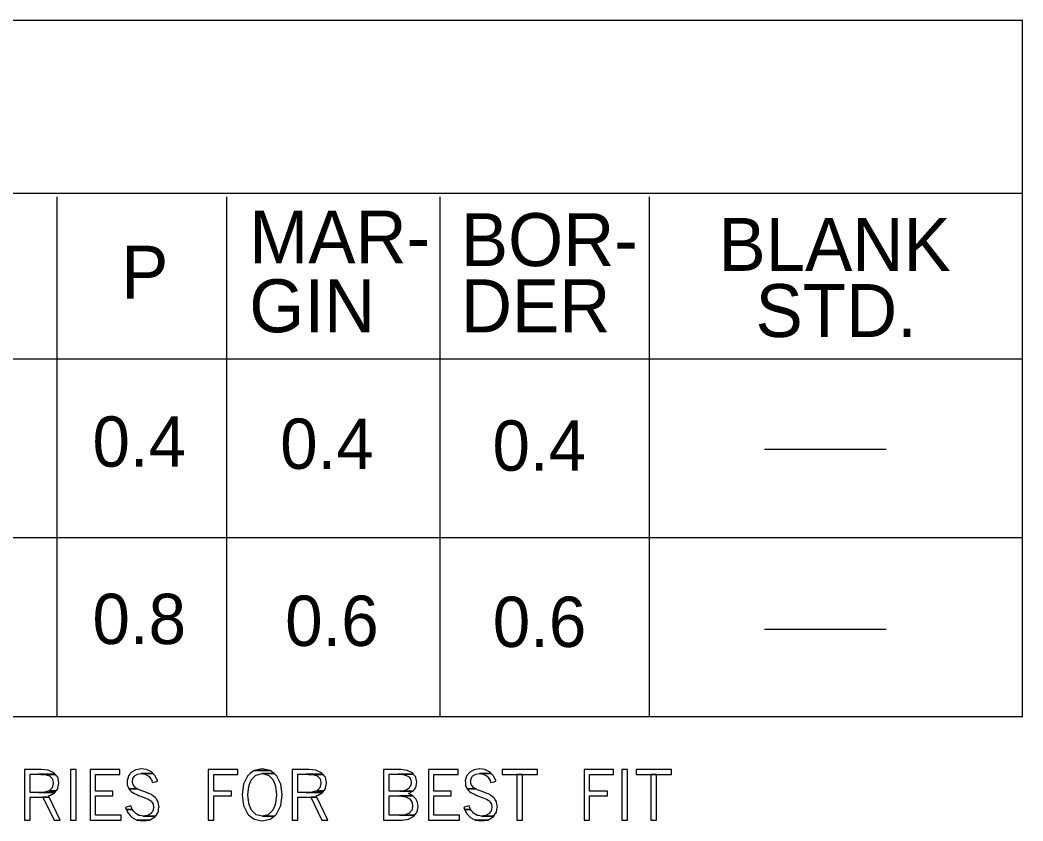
# Model space of a CAD drawing. Extents: x 0.013 to 0.187, y -0.092 to 0.261.
# Drawn here: x 0.13917 to 0.18651, y 0.0569 to 0.09473 of the extents above; entities that cross this region are included whole.
import ezdxf

# ---------------------------------------------------------------- set-up
doc = ezdxf.new("R2010")
doc.units = 0
doc.layers.add('3', color=7, linetype='Continuous')

msp = doc.modelspace()

# ---------------------------------------------------------------- linework, layer by layer
at = {"layer": '3'}
for p, q in [((0.032451, 0.094728), (0.186512, 0.094728)), ((0.186473, 0.094707), (0.186473, 0.061821)), ((0.186512, 0.086538), (0.032451, 0.086538)), ((0.140908, 0.086386), (0.140908, 0.061842)), ((0.148908, 0.086386), (0.148908, 0.061842)), ((0.158976, 0.086386), (0.158976, 0.061842)), ((0.168869, 0.086386), (0.168869, 0.061842)), ((0.032384, 0.078726), (0.186512, 0.078726)), ((0.174312, 0.074459), (0.180062, 0.074459)), ((0.032451, 0.070284), (0.186512, 0.070284)), ((0.174312, 0.065959), (0.180062, 0.065959)), ((0.032519, 0.061842), (0.186512, 0.061842))]:
    msp.add_line(p, q, dxfattribs=at)
for points in [[(0.139376, 0.058024), (0.139376, 0.056942), (0.139636, 0.056942), (0.139636, 0.058024), (0.140533, 0.058024), (0.140503, 0.058086), (0.140605, 0.058122), (0.140792, 0.058228), (0.140806, 0.058246), (0.139636, 0.058246), (0.139636, 0.058249), (0.139636, 0.058264), (0.139636, 0.058332), (0.139636, 0.058428), (0.139636, 0.058472), (0.139636, 0.058676), (0.139636, 0.058696), (0.139636, 0.058887), (0.139636, 0.058964), (0.139636, 0.059034), (0.139636, 0.059093), (0.139636, 0.059104), (0.139636, 0.059106), (0.140828, 0.059106), (0.140768, 0.059179), (0.140492, 0.059298), (0.140175, 0.059326), (0.140046, 0.059329), (0.139376, 0.059329), (0.139376, 0.059326), (0.139376, 0.059298), (0.139376, 0.059179), (0.139376, 0.059106), (0.139376, 0.059104), (0.139376, 0.059093), (0.139376, 0.059034), (0.139376, 0.058964), (0.139376, 0.058887), (0.139376, 0.058696), (0.139376, 0.058676), (0.139376, 0.058472), (0.139376, 0.058428), (0.139376, 0.058332), (0.139376, 0.058264), (0.139376, 0.058249), (0.139376, 0.058246), (0.139376, 0.058228), (0.139376, 0.058122), (0.139376, 0.058086)], [(0.141548, 0.059329), (0.141548, 0.056942), (0.141816, 0.056942), (0.141816, 0.059329)], [(0.142472, 0.057172), (0.142472, 0.056942), (0.143935, 0.056942), (0.143935, 0.057172), (0.142734, 0.057172), (0.142734, 0.058085), (0.143546, 0.058085), (0.143546, 0.058306), (0.142734, 0.058306), (0.142734, 0.059103), (0.143879, 0.059103), (0.143879, 0.059329), (0.142472, 0.059329), (0.142472, 0.059103), (0.142472, 0.058306), (0.142472, 0.058085)], [(0.14428, 0.058465), (0.144302, 0.058415), (0.144717, 0.058415), (0.144621, 0.058465), (0.144532, 0.05857), (0.144499, 0.058609), (0.144476, 0.058715), (0.144467, 0.058756), (0.144472, 0.058784), (0.144475, 0.058806), (0.144484, 0.058856), (0.144485, 0.058862), (0.144493, 0.05891), (0.144563, 0.059016), (0.144575, 0.059034), (0.144586, 0.059041), (0.144602, 0.059051), (0.144712, 0.059118), (0.144715, 0.059119), (0.144885, 0.059146), (0.145444, 0.059146), (0.145385, 0.059208), (0.145365, 0.059229), (0.145165, 0.059325), (0.145133, 0.05934), (0.144879, 0.059367), (0.144879, 0.059367), (0.144722, 0.05934), (0.144632, 0.059325), (0.14446, 0.059229), (0.144422, 0.059208), (0.144372, 0.059146), (0.14435, 0.059119), (0.144349, 0.059118), (0.144294, 0.059051), (0.144286, 0.059041), (0.144283, 0.059034), (0.144278, 0.059016), (0.144247, 0.05891), (0.144233, 0.058862), (0.144231, 0.058856), (0.144216, 0.058806), (0.144217, 0.058784), (0.144219, 0.058756), (0.144222, 0.058715), (0.144229, 0.058609), (0.144232, 0.05857)], [(0.14805, 0.058083), (0.14805, 0.056942), (0.148312, 0.056942), (0.148312, 0.058083), (0.149153, 0.058083), (0.149153, 0.058308), (0.148312, 0.058308), (0.148312, 0.059103), (0.149448, 0.059103), (0.149448, 0.059329), (0.14805, 0.059329), (0.14805, 0.059103), (0.14805, 0.058308)], [(0.150225, 0.05698), (0.150596, 0.056903), (0.150968, 0.05698), (0.151156, 0.057133), (0.150596, 0.057133), (0.150314, 0.057197), (0.150285, 0.057225), (0.150092, 0.057409), (0.150002, 0.057637), (0.149963, 0.057738), (0.149921, 0.058135), (0.149963, 0.058532), (0.150002, 0.058633), (0.150092, 0.058861), (0.150285, 0.059045), (0.150314, 0.059073), (0.150596, 0.059138), (0.151156, 0.059138), (0.150968, 0.05929), (0.150225, 0.05929), (0.150036, 0.059138), (0.149956, 0.059073), (0.149922, 0.059045), (0.149831, 0.058861), (0.149718, 0.058633), (0.149705, 0.058532), (0.149653, 0.058135), (0.149705, 0.057738), (0.149718, 0.057637), (0.149831, 0.057409), (0.149922, 0.057225), (0.149956, 0.057197), (0.150036, 0.057133)], [(0.150596, 0.059367), (0.150225, 0.05929), (0.150968, 0.05929)], [(0.152013, 0.058024), (0.152013, 0.056942), (0.152272, 0.056942), (0.152272, 0.058024), (0.15317, 0.058024), (0.15314, 0.058086), (0.153242, 0.058122), (0.153429, 0.058228), (0.153443, 0.058246), (0.152272, 0.058246), (0.152272, 0.058249), (0.152272, 0.058264), (0.152272, 0.058332), (0.152272, 0.058428), (0.152272, 0.058472), (0.152272, 0.058676), (0.152272, 0.058696), (0.152272, 0.058887), (0.152272, 0.058964), (0.152272, 0.059034), (0.152272, 0.059093), (0.152272, 0.059104), (0.152272, 0.059106), (0.153465, 0.059106), (0.153405, 0.059179), (0.153129, 0.059298), (0.152812, 0.059326), (0.152683, 0.059329), (0.152013, 0.059329), (0.152013, 0.059326), (0.152013, 0.059298), (0.152013, 0.059179), (0.152013, 0.059106), (0.152013, 0.059104), (0.152013, 0.059093), (0.152013, 0.059034), (0.152013, 0.058964), (0.152013, 0.058887), (0.152013, 0.058696), (0.152013, 0.058676), (0.152013, 0.058472), (0.152013, 0.058428), (0.152013, 0.058332), (0.152013, 0.058264), (0.152013, 0.058249), (0.152013, 0.058246), (0.152013, 0.058228), (0.152013, 0.058122), (0.152013, 0.058086)], [(0.156327, 0.056945), (0.156327, 0.056942), (0.157052, 0.056942), (0.157206, 0.056945), (0.157501, 0.056988), (0.157761, 0.057128), (0.157794, 0.057172), (0.156587, 0.057172), (0.156587, 0.057175), (0.156587, 0.057193), (0.156587, 0.057266), (0.156587, 0.057332), (0.156587, 0.05741), (0.156587, 0.057568), (0.156587, 0.057589), (0.156587, 0.057782), (0.156587, 0.057788), (0.156587, 0.057944), (0.156587, 0.057969), (0.156587, 0.058045), (0.156587, 0.058081), (0.156587, 0.058084), (0.157715, 0.058084), (0.157701, 0.058098), (0.15757, 0.058172), (0.157506, 0.0582), (0.157571, 0.058226), (0.157676, 0.058288), (0.157695, 0.058306), (0.156587, 0.058306), (0.156587, 0.058312), (0.156587, 0.058346), (0.156587, 0.058396), (0.156587, 0.05844), (0.156587, 0.058542), (0.156587, 0.058576), (0.156587, 0.058728), (0.156587, 0.058744), (0.156587, 0.058877), (0.156587, 0.05897), (0.156587, 0.059003), (0.156587, 0.059087), (0.156587, 0.059113), (0.156587, 0.059114), (0.15774, 0.059114), (0.15769, 0.059177), (0.157445, 0.059288), (0.157152, 0.059326), (0.156973, 0.059329), (0.156327, 0.059329), (0.156327, 0.059326), (0.156327, 0.059288), (0.156327, 0.059177), (0.156327, 0.059114), (0.156327, 0.059113), (0.156327, 0.059087), (0.156327, 0.059003), (0.156327, 0.05897), (0.156327, 0.058877), (0.156327, 0.058744), (0.156327, 0.058728), (0.156327, 0.058576), (0.156327, 0.058542), (0.156327, 0.05844), (0.156327, 0.058396), (0.156327, 0.058346), (0.156327, 0.058312), (0.156327, 0.058306), (0.156327, 0.058288), (0.156327, 0.058226), (0.156327, 0.0582), (0.156327, 0.058172), (0.156327, 0.058098), (0.156327, 0.058084), (0.156327, 0.058081), (0.156327, 0.058045), (0.156327, 0.057969), (0.156327, 0.057944), (0.156327, 0.057788), (0.156327, 0.057782), (0.156327, 0.057589), (0.156327, 0.057568), (0.156327, 0.05741), (0.156327, 0.057332), (0.156327, 0.057266), (0.156327, 0.057193), (0.156327, 0.057175), (0.156327, 0.057172), (0.156327, 0.057128), (0.156327, 0.056988)], [(0.158442, 0.057172), (0.158442, 0.056942), (0.159905, 0.056942), (0.159905, 0.057172), (0.158704, 0.057172), (0.158704, 0.058085), (0.159516, 0.058085), (0.159516, 0.058306), (0.158704, 0.058306), (0.158704, 0.059103), (0.159849, 0.059103), (0.159849, 0.059329), (0.158442, 0.059329), (0.158442, 0.059103), (0.158442, 0.058306), (0.158442, 0.058085)], [(0.16025, 0.058465), (0.160272, 0.058415), (0.160687, 0.058415), (0.160591, 0.058465), (0.160502, 0.05857), (0.160469, 0.058609), (0.160446, 0.058715), (0.160437, 0.058756), (0.160442, 0.058784), (0.160445, 0.058806), (0.160454, 0.058856), (0.160455, 0.058862), (0.160463, 0.05891), (0.160533, 0.059016), (0.160545, 0.059034), (0.160556, 0.059041), (0.160572, 0.059051), (0.160682, 0.059118), (0.160685, 0.059119), (0.160855, 0.059146), (0.161413, 0.059146), (0.161355, 0.059208), (0.161335, 0.059229), (0.161135, 0.059325), (0.161103, 0.05934), (0.160849, 0.059367), (0.160848, 0.059367), (0.160691, 0.05934), (0.160602, 0.059325), (0.16043, 0.059229), (0.160392, 0.059208), (0.160341, 0.059146), (0.16032, 0.059119), (0.160318, 0.059118), (0.160263, 0.059051), (0.160255, 0.059041), (0.160253, 0.059034), (0.160248, 0.059016), (0.160217, 0.05891), (0.160202, 0.058862), (0.160201, 0.058856), (0.160186, 0.058806), (0.160187, 0.058784), (0.160189, 0.058756), (0.160192, 0.058715), (0.160199, 0.058609), (0.160202, 0.05857)], [(0.161925, 0.059329), (0.161925, 0.059099), (0.163587, 0.059099), (0.163587, 0.059329)], [(0.165791, 0.058083), (0.165791, 0.056942), (0.166053, 0.056942), (0.166053, 0.058083), (0.166895, 0.058083), (0.166895, 0.058308), (0.166053, 0.058308), (0.166053, 0.059103), (0.167189, 0.059103), (0.167189, 0.059329), (0.165791, 0.059329), (0.165791, 0.059103), (0.165791, 0.058308)], [(0.167578, 0.059329), (0.167578, 0.056942), (0.167845, 0.056942), (0.167845, 0.059329)], [(0.168255, 0.059329), (0.168255, 0.059099), (0.169917, 0.059099), (0.169917, 0.059329)], [(0.140154, 0.059104), (0.140342, 0.059093), (0.14084, 0.059093), (0.140831, 0.059104), (0.14083, 0.059104), (0.140828, 0.059106), (0.140043, 0.059106)], [(0.140642, 0.058428), (0.140542, 0.058332), (0.140873, 0.058332), (0.140947, 0.058428), (0.140956, 0.058472), (0.140995, 0.058676), (0.140999, 0.058696), (0.140962, 0.058887), (0.140947, 0.058964), (0.140889, 0.059034), (0.14084, 0.059093), (0.140341, 0.059093), (0.14055, 0.059034), (0.140616, 0.058964), (0.140691, 0.058887), (0.140728, 0.058696), (0.140732, 0.058676), (0.140687, 0.058472)], [(0.145404, 0.058756), (0.14542, 0.058715), (0.145561, 0.058756), (0.145658, 0.058784), (0.145651, 0.058806), (0.145635, 0.058856), (0.145633, 0.058862), (0.145608, 0.05891), (0.145552, 0.059016), (0.145543, 0.059034), (0.145539, 0.059041), (0.145534, 0.059051), (0.14547, 0.059118), (0.145469, 0.059119), (0.145444, 0.059146), (0.144885, 0.059146), (0.145057, 0.059119), (0.145067, 0.059118), (0.145185, 0.059051), (0.145203, 0.059041), (0.145215, 0.059034), (0.145248, 0.059016), (0.145326, 0.05891), (0.145361, 0.058862), (0.145366, 0.058856), (0.145385, 0.058806), (0.145394, 0.058784)], [(0.150877, 0.057197), (0.150596, 0.057133), (0.151156, 0.057133), (0.151237, 0.057197), (0.151236, 0.057197), (0.151271, 0.057225), (0.151362, 0.057409), (0.151475, 0.057637), (0.151488, 0.057738), (0.151539, 0.058135), (0.151488, 0.058532), (0.151475, 0.058633), (0.151362, 0.058861), (0.151271, 0.059045), (0.151237, 0.059073), (0.151236, 0.059073), (0.151156, 0.059138), (0.150595, 0.059138), (0.150877, 0.059073), (0.150906, 0.059045), (0.151099, 0.058861), (0.151189, 0.058633), (0.151229, 0.058532), (0.151271, 0.058135), (0.151229, 0.057738), (0.151189, 0.057637), (0.151099, 0.057409), (0.150906, 0.057225)], [(0.152791, 0.059104), (0.152979, 0.059093), (0.153477, 0.059093), (0.153467, 0.059104), (0.153467, 0.059104), (0.153465, 0.059106), (0.15268, 0.059106)], [(0.153278, 0.058428), (0.153179, 0.058332), (0.15351, 0.058332), (0.153584, 0.058428), (0.153593, 0.058472), (0.153632, 0.058676), (0.153636, 0.058696), (0.153599, 0.058887), (0.153584, 0.058964), (0.153526, 0.059034), (0.153477, 0.059093), (0.152978, 0.059093), (0.153186, 0.059034), (0.153253, 0.058964), (0.153328, 0.058887), (0.153365, 0.058696), (0.153369, 0.058676), (0.153324, 0.058472)], [(0.157022, 0.059114), (0.157123, 0.059113), (0.15774, 0.059113), (0.15774, 0.059114)], [(0.157359, 0.058346), (0.157191, 0.058312), (0.157701, 0.058312), (0.157737, 0.058346), (0.15779, 0.058396), (0.157814, 0.05844), (0.15787, 0.058542), (0.157875, 0.058576), (0.157874, 0.058576), (0.157895, 0.058728), (0.157898, 0.058744), (0.157871, 0.058877), (0.157853, 0.05897), (0.157827, 0.059003), (0.157761, 0.059087), (0.15774, 0.059113), (0.157123, 0.059113), (0.15732, 0.059087), (0.157507, 0.059003), (0.157531, 0.05897), (0.157601, 0.058877), (0.157627, 0.058744), (0.15763, 0.058728), (0.157608, 0.058576), (0.157587, 0.058542), (0.157522, 0.05844), (0.157446, 0.058396)], [(0.161374, 0.058756), (0.16139, 0.058715), (0.161531, 0.058756), (0.161628, 0.058784), (0.161621, 0.058806), (0.161605, 0.058856), (0.161603, 0.058862), (0.161578, 0.05891), (0.161522, 0.059016), (0.161513, 0.059034), (0.161509, 0.059041), (0.161504, 0.059051), (0.16144, 0.059118), (0.161439, 0.059119), (0.161413, 0.059146), (0.160854, 0.059146), (0.161027, 0.059119), (0.161037, 0.059118), (0.161155, 0.059051), (0.161173, 0.059041), (0.161185, 0.059034), (0.161218, 0.059016), (0.161295, 0.05891), (0.161331, 0.058862), (0.161336, 0.058856), (0.161355, 0.058806), (0.161363, 0.058784)], [(0.16262, 0.059099), (0.16262, 0.056942), (0.162891, 0.056942), (0.162891, 0.059099)], [(0.16895, 0.059099), (0.16895, 0.056942), (0.16922, 0.056942), (0.16922, 0.059099)], [(0.14012, 0.058249), (0.140034, 0.058246), (0.140806, 0.058246), (0.140809, 0.058249), (0.140821, 0.058264), (0.140873, 0.058332), (0.140542, 0.058332), (0.140324, 0.058264)], [(0.145168, 0.057156), (0.144976, 0.057131), (0.145563, 0.057131), (0.14558, 0.057156), (0.145586, 0.057166), (0.145633, 0.057236), (0.145642, 0.057251), (0.145642, 0.057251), (0.145654, 0.057269), (0.145687, 0.057318), (0.145696, 0.057373), (0.145702, 0.057406), (0.145709, 0.057446), (0.145724, 0.057531), (0.145725, 0.057541), (0.145726, 0.057546), (0.14573, 0.057563), (0.145709, 0.057702), (0.145694, 0.057798), (0.145675, 0.05783), (0.145612, 0.057933), (0.145571, 0.058001), (0.145547, 0.058018), (0.145418, 0.058113), (0.145374, 0.058145), (0.145249, 0.058198), (0.14513, 0.05825), (0.145009, 0.058293), (0.144828, 0.058359), (0.144717, 0.058415), (0.144302, 0.058415), (0.144354, 0.058359), (0.144415, 0.058293), (0.144484, 0.05825), (0.144564, 0.058198), (0.144686, 0.058145), (0.14476, 0.058113), (0.145018, 0.058018), (0.145056, 0.058001), (0.145215, 0.057933), (0.145368, 0.05783), (0.145389, 0.057798), (0.14545, 0.057702), (0.145471, 0.057563), (0.145474, 0.057546), (0.145473, 0.057541), (0.14547, 0.057531), (0.145453, 0.057446), (0.145444, 0.057406), (0.145438, 0.057373), (0.145393, 0.057318), (0.145353, 0.057269), (0.145338, 0.057251), (0.145326, 0.057236), (0.145187, 0.057166)], [(0.152757, 0.058249), (0.152671, 0.058246), (0.153443, 0.058246), (0.153446, 0.058249), (0.153457, 0.058264), (0.15351, 0.058332), (0.153178, 0.058332), (0.152961, 0.058264)], [(0.15719, 0.058312), (0.157095, 0.058306), (0.157695, 0.058306), (0.157701, 0.058312)], [(0.161137, 0.057156), (0.160946, 0.057131), (0.161533, 0.057131), (0.16155, 0.057156), (0.161556, 0.057166), (0.161602, 0.057236), (0.161612, 0.057251), (0.161612, 0.057251), (0.161624, 0.057269), (0.161657, 0.057318), (0.161666, 0.057373), (0.161672, 0.057406), (0.161679, 0.057446), (0.161694, 0.057531), (0.161695, 0.057541), (0.161696, 0.057546), (0.161699, 0.057563), (0.161678, 0.057702), (0.161664, 0.057798), (0.161645, 0.05783), (0.161582, 0.057933), (0.161541, 0.058001), (0.161517, 0.058018), (0.161387, 0.058113), (0.161344, 0.058145), (0.161219, 0.058198), (0.1611, 0.05825), (0.160979, 0.058293), (0.160798, 0.058359), (0.160687, 0.058415), (0.160272, 0.058415), (0.160324, 0.058359), (0.160385, 0.058293), (0.160454, 0.05825), (0.160534, 0.058198), (0.160656, 0.058145), (0.16073, 0.058113), (0.160988, 0.058018), (0.161026, 0.058001), (0.161185, 0.057933), (0.161338, 0.05783), (0.161358, 0.057798), (0.16142, 0.057702), (0.161441, 0.057563), (0.161444, 0.057546), (0.161442, 0.057541), (0.16144, 0.057531), (0.161423, 0.057446), (0.161414, 0.057406), (0.161408, 0.057373), (0.161363, 0.057318), (0.161323, 0.057269), (0.161308, 0.057251), (0.161296, 0.057236), (0.161157, 0.057166)], [(0.140249, 0.058024), (0.140772, 0.056942), (0.141063, 0.056942), (0.140533, 0.058024)], [(0.152886, 0.058024), (0.153409, 0.056942), (0.1537, 0.056942), (0.15317, 0.058024)], [(0.157343, 0.057193), (0.157169, 0.057175), (0.157796, 0.057175), (0.15781, 0.057193), (0.157865, 0.057266), (0.157915, 0.057332), (0.157931, 0.05741), (0.157964, 0.057568), (0.157961, 0.057589), (0.157935, 0.057782), (0.157934, 0.057788), (0.15785, 0.057944), (0.157837, 0.057969), (0.157756, 0.058045), (0.157718, 0.058081), (0.157715, 0.058084), (0.157077, 0.058084), (0.157196, 0.058081), (0.157378, 0.058045), (0.157517, 0.057969), (0.157561, 0.057944), (0.157668, 0.057788), (0.157672, 0.057782), (0.157695, 0.057589), (0.157691, 0.057568), (0.157657, 0.05741), (0.157588, 0.057332), (0.15753, 0.057266)], [(0.144149, 0.057531), (0.14418, 0.057446), (0.144468, 0.057446), (0.144425, 0.057531), (0.144421, 0.057541), (0.14442, 0.057546), (0.144414, 0.057563), (0.144414, 0.057563), (0.144396, 0.057621), (0.144395, 0.057621), (0.144215, 0.057563), (0.144162, 0.057546), (0.144146, 0.057541)], [(0.144457, 0.057064), (0.144687, 0.056947), (0.145283, 0.056947), (0.145481, 0.057064), (0.145543, 0.0571), (0.145563, 0.057131), (0.144976, 0.057131), (0.144833, 0.057156), (0.144833, 0.057156), (0.144777, 0.057166), (0.144663, 0.057236), (0.144639, 0.057251), (0.144609, 0.057269), (0.144566, 0.057318), (0.144518, 0.057373), (0.144517, 0.057373), (0.144489, 0.057406), (0.144468, 0.057446), (0.14418, 0.057446), (0.1442, 0.057406), (0.144218, 0.057373), (0.144246, 0.057318), (0.144271, 0.057269), (0.144281, 0.057251), (0.144294, 0.057236), (0.144361, 0.057166), (0.14437, 0.057156), (0.144394, 0.057131), (0.144423, 0.0571)], [(0.160119, 0.057531), (0.16015, 0.057446), (0.160438, 0.057446), (0.160394, 0.057531), (0.160391, 0.057541), (0.160389, 0.057546), (0.160384, 0.057563), (0.160384, 0.057563), (0.160365, 0.057621), (0.160365, 0.057621), (0.160184, 0.057563), (0.160132, 0.057546), (0.160116, 0.057541)], [(0.160427, 0.057064), (0.160657, 0.056947), (0.161253, 0.056947), (0.161451, 0.057064), (0.161513, 0.0571), (0.161533, 0.057131), (0.160946, 0.057131), (0.160803, 0.057156), (0.160803, 0.057156), (0.160747, 0.057166), (0.160633, 0.057236), (0.160609, 0.057251), (0.160579, 0.057269), (0.160536, 0.057318), (0.160488, 0.057373), (0.160487, 0.057373), (0.160459, 0.057406), (0.160438, 0.057446), (0.16015, 0.057446), (0.16017, 0.057406), (0.160188, 0.057373), (0.160216, 0.057318), (0.160241, 0.057269), (0.160251, 0.057251), (0.160264, 0.057236), (0.160331, 0.057166), (0.16034, 0.057156), (0.160364, 0.057131), (0.160393, 0.0571)], [(0.144692, 0.056946), (0.144969, 0.056903), (0.145282, 0.056946), (0.145283, 0.056947), (0.144687, 0.056947)], [(0.157169, 0.057175), (0.157078, 0.057172), (0.157794, 0.057172), (0.157796, 0.057175)], [(0.160662, 0.056946), (0.160939, 0.056903), (0.161252, 0.056946), (0.161253, 0.056947), (0.160657, 0.056947)]]:
    msp.add_lwpolyline(points, close=True, dxfattribs=at)

# ---------------------------------------------------------------- texts
for s, height, p in [('MAR-', 0.0024998, (0.149988, 0.083232)), ('BOR-', 0.0024998, (0.159977, 0.083107)), ('BLANK', 0.0024998, (0.172138, 0.082883)), ('P', 0.0025, (0.143939, 0.081571)), ('GIN', 0.0024998, (0.149988, 0.079983)), ('DER', 0.0024998, (0.159977, 0.079982)), ('STD.', 0.0024998, (0.173888, 0.079758)), ('0.4', 0.0023752, (0.142587, 0.073633)), ('0.4', 0.0023752, (0.151447, 0.073532)), ('0.4', 0.0023752, (0.161471, 0.073445)), ('0.8', 0.0023752, (0.142586, 0.065258)), ('0.6', 0.0023752, (0.151682, 0.06517)), ('0.6', 0.0023752, (0.161483, 0.06512))]:
    msp.add_text(s, height=height, dxfattribs=at).set_placement(p)

doc.saveas('drawing.dxf')
